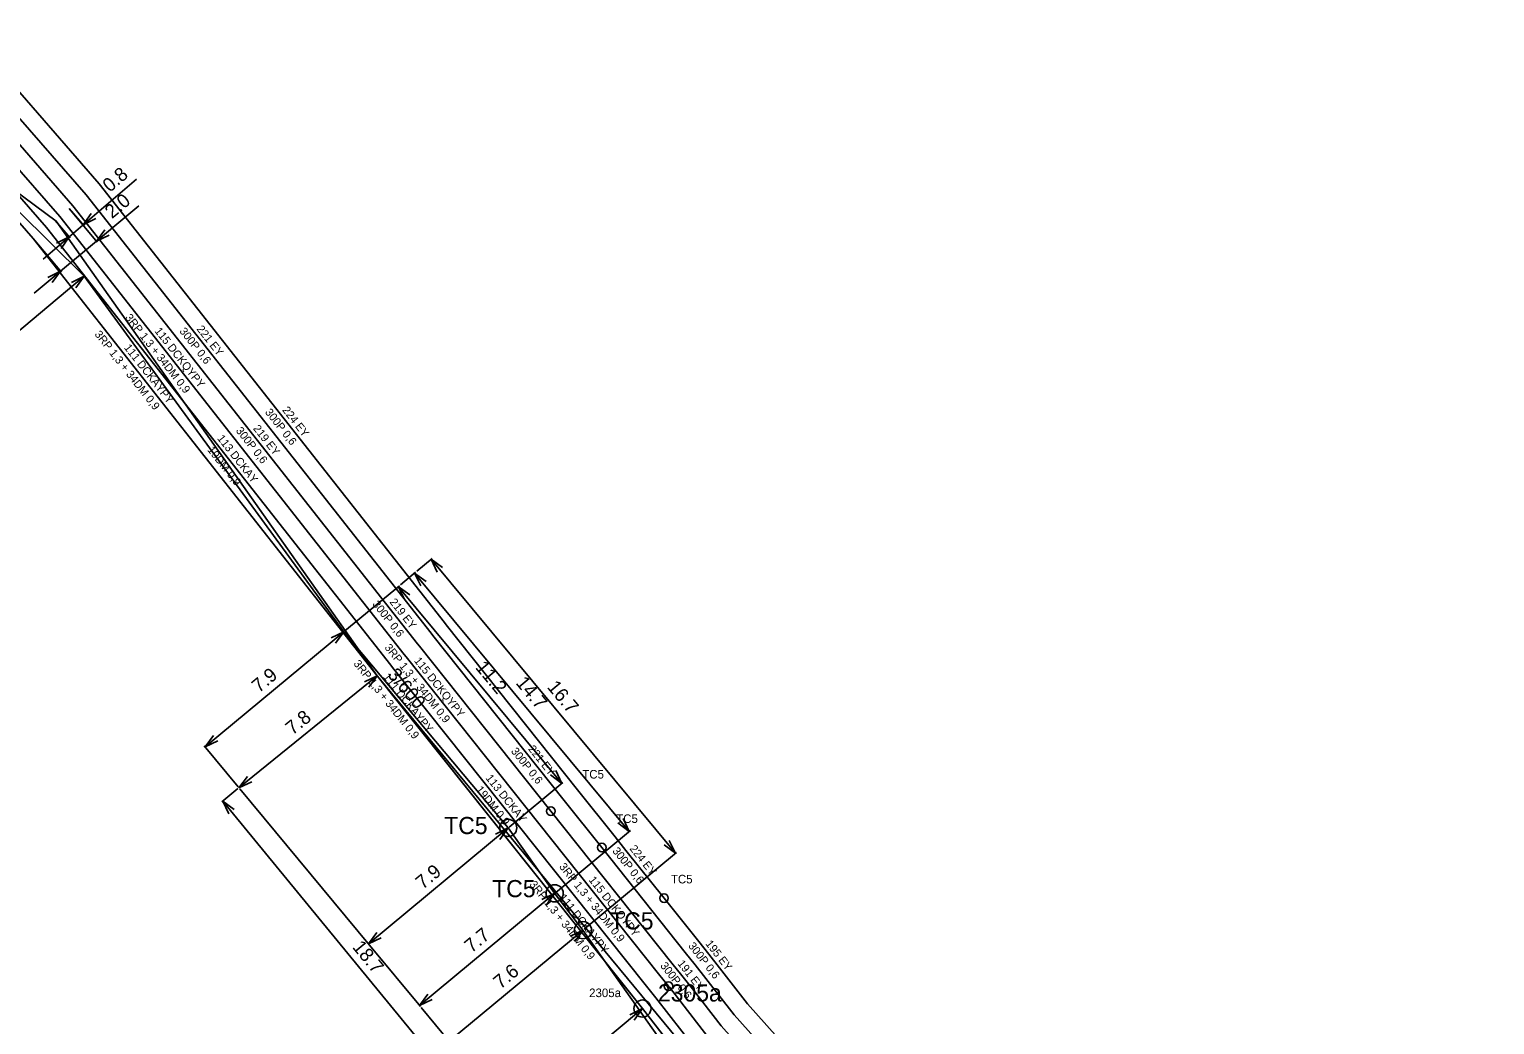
# Model space of a CAD drawing. Extents: x -756413 to -755757, y -1139003 to -1138237.
# Drawn here: x -756220.1 to -756156, y -1138347.7 to -1138304.2 of the extents above; entities that cross this region are included whole.
import ezdxf

# ---------------------------------------------------------------- set-up
doc = ezdxf.new("R2010")
doc.units = 0
for name, color, linetype in [('f004_popis_kab_zil', 7, 'Continuous'), ('f004_popisy_mts', 7, 'Continuous'), ('f004_rezervy_spojky', 7, 'Continuous'), ('f006_osa_trasy', 7, 'Continuous'), ('f006_stp_koty', 7, 'Continuous'), ('f307_kabel_metal', 7, 'Continuous'), ('f307_kabel_metal_ann', 7, 'Continuous'), ('f307_spojka_metal', 7, 'Continuous'), ('f307_spojka_metal_ann', 7, 'Continuous')]:
    doc.layers.add(name, color=color, linetype=linetype)

msp = doc.modelspace()

# ---------------------------------------------------------------- linework, layer by layer
at = {"layer": 'f004_rezervy_spojky'}
for centre in [(-756199.11, -1138339.08), (-756197.08, -1138341.94), (-756195.84, -1138343.55), (-756193.24, -1138346.98)]:
    msp.add_circle(centre, 0.375, dxfattribs=at)
at = {"layer": 'f006_osa_trasy'}
for p, q in [((-756204.84, -1138332.43), (-756184.01, -1138357.6)), ((-756204.84, -1138332.43), (-756193.24, -1138346.98)), ((-756199.11, -1138339.08), (-756197.08, -1138341.94)), ((-756197.08, -1138341.94), (-756195.84, -1138343.55)), ((-756193.24, -1138346.98), (-756191.54, -1138349.16))]:
    msp.add_line(p, q, dxfattribs=at)
for points in [[(-756253.43, -1138329.81), (-756236.07, -1138320.55), (-756230.66, -1138313.13), (-756226.19, -1138308.44), (-756224.71, -1138308.25), (-756222.03, -1138310.66), (-756217.66, -1138314.96), (-756206.3, -1138330.51), (-756199.11, -1138339.08)], [(-756223.6, -1138309.06), (-756218.89, -1138312.55), (-756204.84, -1138332.43)], [(-756204.84, -1138332.43), (-756219.89, -1138313.31), (-756223.6, -1138309.06)], [(-756195.84, -1138343.55), (-756185.35, -1138358.4), (-756177.88, -1138364.69), (-756170.53, -1138375.55), (-756161.61, -1138387.83), (-756142.93, -1138413.51), (-756121.74, -1138435.57), (-756109.6, -1138449.6), (-756100.9, -1138454.08), (-756099.19, -1138454.87), (-756076.56, -1138471.66)]]:
    msp.add_lwpolyline(points, dxfattribs=at)
at = {"layer": 'f006_stp_koty'}
for p, q in [((-756215.374, -1138310.711), (-756219.452, -1138314.211)), ((-756215.272, -1138311.875), (-756219.844, -1138315.7)), ((-756218.325, -1138311.996), (-756217.089, -1138313.474)), ((-756218.324, -1138311.995), (-756217.669, -1138312.759)), ((-756218.93, -1138312.515), (-756218.275, -1138313.279)), ((-756219.891, -1138313.306), (-756218.655, -1138314.784)), ((-756224.554, -1138320.71), (-756217.66, -1138314.96)), ((-756203.114, -1138327.857), (-756202.438, -1138327.295)), ((-756202.484, -1138327.333), (-756191.797, -1138340.188)), ((-756203.827, -1138328.45), (-756203.161, -1138327.896)), ((-756203.207, -1138327.934), (-756193.815, -1138339.231)), ((-756206.252, -1138330.466), (-756203.873, -1138328.488)), ((-756203.919, -1138328.527), (-756196.765, -1138337.132)), ((-756212.371, -1138335.542), (-756206.298, -1138330.505)), ((-756210.892, -1138337.326), (-756204.84, -1138332.43)), ((-756210.93, -1138337.279), (-756212.409, -1138335.496)), ((-756199.065, -1138339.044), (-756196.719, -1138337.094)), ((-756210.938, -1138337.364), (-756211.646, -1138337.945)), ((-756210.853, -1138337.372), (-756205.187, -1138344.201)), ((-756211.599, -1138337.907), (-756199.728, -1138352.364)), ((-756205.226, -1138344.155), (-756199.111, -1138339.083)), ((-756197.303, -1138342.131), (-756193.769, -1138339.193)), ((-756195.79, -1138343.507), (-756191.751, -1138340.149)), ((-756202.993, -1138346.847), (-756197.078, -1138341.94)), ((-756197.081, -1138341.936), (-756197.039, -1138341.986)), ((-756201.698, -1138348.408), (-756195.837, -1138343.545)), ((-756205.187, -1138344.202), (-756202.954, -1138346.893)), ((-756202.916, -1138346.94), (-756201.66, -1138348.454)), ((-756199.025, -1138351.788), (-756193.236, -1138346.984)), ((-756193.251, -1138346.966), (-756193.198, -1138347.03))]:
    msp.add_line(p, q, dxfattribs=at)
for points in [[(-756217.154, -1138312.437), (-756217.708, -1138312.714), (-756217.35, -1138312.209)], [(-756218.867, -1138313.51), (-756218.314, -1138313.234), (-756218.671, -1138313.738)], [(-756216.57, -1138313.158), (-756217.127, -1138313.428), (-756216.763, -1138312.927)], [(-756219.249, -1138315.007), (-756218.693, -1138314.738), (-756219.056, -1138315.238)], [(-756218.216, -1138315.229), (-756217.66, -1138314.96), (-756218.024, -1138315.459)], [(-756202.215, -1138327.89), (-756202.484, -1138327.333), (-756201.985, -1138327.698)], [(-756202.938, -1138328.491), (-756203.207, -1138327.934), (-756202.708, -1138328.299)], [(-756203.65, -1138329.084), (-756203.919, -1138328.527), (-756203.42, -1138328.892)], [(-756206.855, -1138330.772), (-756206.298, -1138330.505), (-756206.664, -1138331.003)], [(-756205.4, -1138332.69), (-756204.84, -1138332.43), (-756205.212, -1138332.923)], [(-756211.813, -1138335.274), (-756212.371, -1138335.542), (-756212.004, -1138335.043)], [(-756210.331, -1138337.065), (-756210.892, -1138337.326), (-756210.519, -1138336.832)], [(-756197.033, -1138336.574), (-756196.765, -1138337.132), (-756197.263, -1138336.766)], [(-756211.334, -1138338.465), (-756211.599, -1138337.907), (-756211.102, -1138338.275)], [(-756194.083, -1138338.673), (-756193.815, -1138339.231), (-756194.313, -1138338.865)], [(-756199.668, -1138339.35), (-756199.111, -1138339.083), (-756199.477, -1138339.581)], [(-756192.065, -1138339.63), (-756191.797, -1138340.188), (-756192.295, -1138339.822)], [(-756197.635, -1138342.207), (-756197.078, -1138341.94), (-756197.444, -1138342.438)], [(-756204.668, -1138343.887), (-756205.226, -1138344.155), (-756204.859, -1138343.656)], [(-756196.394, -1138343.812), (-756195.837, -1138343.545), (-756196.203, -1138344.043)], [(-756202.435, -1138346.579), (-756202.993, -1138346.847), (-756202.626, -1138346.348)], [(-756193.793, -1138347.251), (-756193.236, -1138346.984), (-756193.601, -1138347.482)]]:
    msp.add_lwpolyline(points, dxfattribs=at)
at = {"layer": 'f307_kabel_metal'}
for points in [[(-756222.9, -1138304.16), (-756217, -1138310.915), (-756201.901, -1138330.101), (-756201.821, -1138330.201), (-756196.074, -1138337.411), (-756194.429, -1138339.474), (-756193.961, -1138340.061), (-756192.296, -1138342.149)], [(-756223.04, -1138305.14), (-756217.578, -1138311.394), (-756202.488, -1138330.568), (-756202.407, -1138330.669), (-756196.66, -1138337.879), (-756195.015, -1138339.942)], [(-756270.019, -1138306.197), (-756266.653, -1138308.817), (-756266.11, -1138309.24), (-756262.64, -1138315.59), (-756261.9, -1138316.99), (-756259.83, -1138323.74), (-756255.203, -1138328.655), (-756254.69, -1138329.2), (-756254.31, -1138329.67), (-756251.17, -1138328.82), (-756246.873, -1138326.389), (-756246.22, -1138326.02), (-756236.07, -1138320.55), (-756229.85, -1138314.13), (-756227.1, -1138311.3), (-756223.6, -1138309.06), (-756219.89, -1138313.31), (-756204.84, -1138332.43), (-756204.754, -1138332.538), (-756193.708, -1138346.394), (-756193.24, -1138346.98), (-756191.54, -1138349.16)], [(-756223.18, -1138306.12), (-756218.156, -1138311.873), (-756203.076, -1138331.033), (-756202.994, -1138331.136), (-756197.246, -1138338.346)], [(-756223.32, -1138307.1), (-756218.734, -1138312.352), (-756203.664, -1138331.499), (-756203.58, -1138331.604), (-756192.536, -1138345.458), (-756192.101, -1138346.002)], [(-756261.252, -1138316.611), (-756261.204, -1138316.702), (-756259.164, -1138323.353), (-756254.657, -1138328.141), (-756254.125, -1138328.707), (-756254.034, -1138328.818), (-756251.457, -1138328.121), (-756247.242, -1138325.736), (-756246.582, -1138325.363), (-756236.528, -1138319.945), (-756230.388, -1138313.608), (-756227.577, -1138310.715), (-756223.46, -1138308.08), (-756219.312, -1138312.831), (-756204.252, -1138331.964), (-756204.167, -1138332.071), (-756193.122, -1138345.926), (-756192.651, -1138346.515), (-756190.949, -1138348.699), (-756183.432, -1138357.122)], [(-756197.246, -1138338.346), (-756191.95, -1138344.99), (-756191.515, -1138345.534), (-756191.053, -1138346.124), (-756189.797, -1138347.737), (-756182.307, -1138356.129), (-756182.289, -1138356.151), (-756175.756, -1138363.868), (-756166.892, -1138376.919), (-756164.688, -1138380.032), (-756164.264, -1138380.619), (-756160.419, -1138385.809), (-756134.721, -1138415.912)], [(-756195.015, -1138339.942), (-756191.364, -1138344.522), (-756190.927, -1138345.069), (-756190.462, -1138345.662), (-756189.221, -1138347.256), (-756181.737, -1138355.642), (-756181.713, -1138355.671), (-756175.158, -1138363.414), (-756166.276, -1138376.492), (-756164.078, -1138379.596), (-756163.659, -1138380.176), (-756159.832, -1138385.342), (-756134.151, -1138415.425)], [(-756192.296, -1138342.149), (-756190.778, -1138344.054), (-756190.339, -1138344.604), (-756189.871, -1138345.2), (-756188.645, -1138346.775), (-756181.168, -1138355.153), (-756181.138, -1138355.19), (-756174.56, -1138362.96), (-756165.66, -1138376.065), (-756163.468, -1138379.16), (-756163.054, -1138379.733), (-756159.245, -1138384.875), (-756133.581, -1138414.937)], [(-756192.101, -1138346.002), (-756192.062, -1138346.05), (-756190.373, -1138348.218), (-756182.872, -1138356.623), (-756182.86, -1138356.637), (-756176.354, -1138364.322), (-756167.508, -1138377.346), (-756165.298, -1138380.468), (-756164.869, -1138381.062), (-756161.006, -1138386.276), (-756135.291, -1138416.4), (-756134.804, -1138416.968), (-756118.54, -1138435.935), (-756118.06, -1138436.494)]]:
    msp.add_lwpolyline(points, dxfattribs=at)
at = {"layer": 'f307_spojka_metal'}
for centre in [(-756197.246, -1138338.346), (-756195.015, -1138339.942), (-756192.296, -1138342.149), (-756192.101, -1138346.002)]:
    msp.add_circle(centre, 0.188, dxfattribs=at)

# ---------------------------------------------------------------- texts
at = {"layer": 'f004_popis_kab_zil'}
msp.add_text('3/600', height=0.6, rotation=309.96, dxfattribs=at).set_placement((-756204.42, -1138332.4))
at = {"layer": 'f004_popisy_mts'}
for s, p in [('TC5', (-756201.91, -1138339.35)), ('TC5', (-756199.81, -1138342.11)), ('TC5', (-756194.65, -1138343.52)), ('2305a', (-756192.56, -1138346.67))]:
    msp.add_text(s, height=0.75, dxfattribs=at).set_placement(p)
at = {"layer": 'f006_stp_koty'}
for s, rotation, p in [('0.8', 40.63, (-756216.538, -1138311.314)), ('2.0', 39.91, (-756216.443, -1138312.463)), ('11.2', 309.74, (-756200.578, -1138332.077)), ('7.9', 39.68, (-756210.015, -1138333.199)), ('14.7', 309.74, (-756198.811, -1138332.752)), ('16.7', 309.74, (-756197.437, -1138332.935)), ('7.8', 38.97, (-756208.549, -1138335.044)), ('7.9', 39.68, (-756202.849, -1138341.795)), ('7.7', 39.68, (-756200.717, -1138344.57)), ('18.7', 309.39, (-756205.959, -1138344.301)), ('7.6', 39.68, (-756199.448, -1138346.153))]:
    msp.add_text(s, height=0.6, rotation=rotation, dxfattribs=at).set_placement(p)
at = {"layer": 'f307_kabel_metal_ann'}
for s, rotation, p in [(' 3RP 1,3 + 34DM 0,9', 308.21, (-756215.972, -1138316.67)), ('115 DCKQYPY', 308.21, (-756214.601, -1138317.36)), (' 300P 0,6', 308.2, (-756213.595, -1138317.264)), ('221 EY', 308.2, (-756212.761, -1138317.272)), (' 3RP 1,3 + 34DM 0,9', 308.21, (-756217.308, -1138317.399)), ('111 DCKAYPY', 308.21, (-756215.937, -1138318.089)), (' 300P 0,6', 308.2, (-756209.851, -1138320.807)), ('224 EY', 308.2, (-756209.017, -1138320.815)), (' 300P 0,6', 308.2, (-756211.126, -1138321.614)), ('219 EY', 308.2, (-756210.292, -1138321.622)), ('113 DCKAY', 308.21, (-756211.862, -1138322.054)), (' 19DM 0,9', 308.21, (-756212.373, -1138322.455)), (' 300P 0,6', 308.2, (-756205.153, -1138329.202)), ('219 EY', 308.2, (-756204.319, -1138329.21)), (' 3RP 1,3 + 34DM 0,9', 308.56, (-756204.623, -1138331.098)), (' 3RP 1,3 + 34DM 0,9', 308.56, (-756205.979, -1138331.804)), ('115 DCKQYPY', 308.56, (-756203.248, -1138331.78)), ('111 DCKAYPY', 308.56, (-756204.604, -1138332.486)), (' 300P 0,6', 308.56, (-756199.092, -1138335.631)), ('221 EY', 308.56, (-756198.258, -1138335.634)), ('113 DCKAY', 308.56, (-756200.119, -1138336.908)), (' 19DM 0,9', 308.56, (-756200.629, -1138337.312)), (' 300P 0,6', 308.57, (-756194.656, -1138339.992)), ('224 EY', 308.57, (-756193.822, -1138339.995)), (' 3RP 1,3 + 34DM 0,9', 308.56, (-756196.983, -1138340.681)), (' 3RP 1,3 + 34DM 0,9', 308.56, (-756198.283, -1138341.457)), ('115 DCKQYPY', 308.56, (-756195.608, -1138341.363)), ('111 DCKAYPY', 308.56, (-756196.908, -1138342.139)), (' 300P 0,6', 308.14, (-756191.337, -1138344.142)), ('195 EY', 308.14, (-756190.503, -1138344.152)), (' 300P 0,6', 308.06, (-756192.56, -1138345.01)), ('191 EY', 308.06, (-756191.726, -1138345.021))]:
    msp.add_text(s, height=0.35, rotation=rotation, dxfattribs=at).set_placement(p)
at = {"layer": 'f307_spojka_metal_ann'}
for s, p in [('TC5', (-756195.871, -1138336.921)), ('TC5', (-756194.387, -1138338.864)), ('TC5', (-756191.994, -1138341.507)), ('2305a', (-756195.571, -1138346.479))]:
    msp.add_text(s, height=0.375, dxfattribs=at).set_placement(p)

doc.saveas('drawing.dxf')
